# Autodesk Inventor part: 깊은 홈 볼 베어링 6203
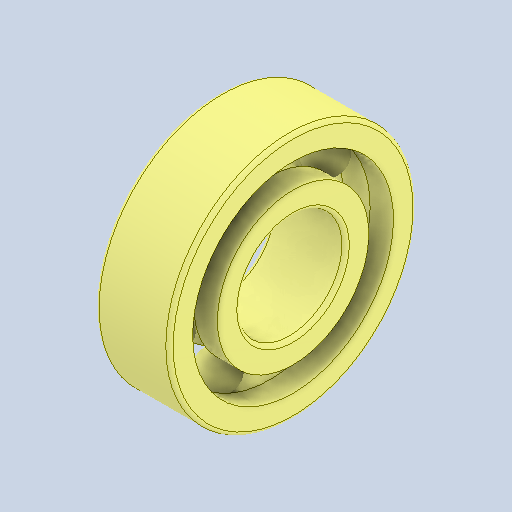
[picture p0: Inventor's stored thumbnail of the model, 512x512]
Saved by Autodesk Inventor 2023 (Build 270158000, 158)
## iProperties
Created: 2025-03
Part Number: 깊은 홈 볼 베어링 6203
Material: 강철, 연강
Description: 깊은 그루브 볼 베어링
Document SubType Name: Modeling
Designer: Admin
Density: 7.85 g/cm^3
Appearance: 기본값
Author: jhkim
Sending System: Autodesk Inventor 2025
Preprocessor: ST-DEVELOPER v20
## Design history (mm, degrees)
feature "Solid1"
feature "Solid1:1"
feature "Solid1:2"
feature "Solid1:3"
feature "Solid1:4"
feature "Solid1:5"
feature "Solid1:6"
feature "Solid1:7"
feature "Solid1:8"
node "솔리드1"
node "솔리드2"
node "솔리드3"
node "솔리드4"
node "솔리드5"
node "솔리드6"
node "솔리드7"
node "솔리드8"
node "솔리드9"
